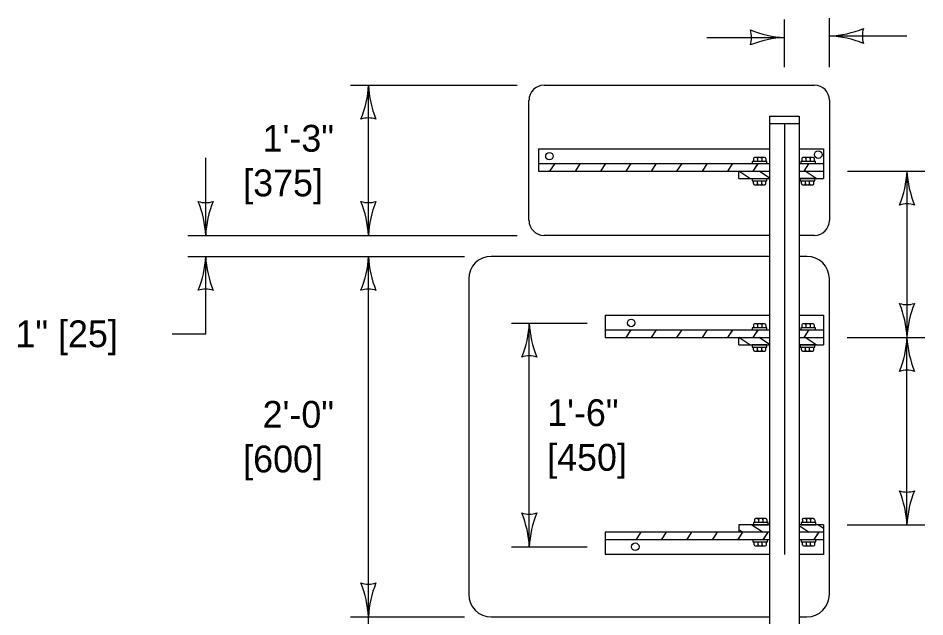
# Model space of a CAD drawing. Extents: x 49991.4 to 50021, y 49987.6 to 50011.4.
# Drawn here: x 50009.026 to 50011.056, y 49996.384 to 49997.726 of the extents above; entities that cross this region are included whole.
import ezdxf

# ---------------------------------------------------------------- set-up
doc = ezdxf.new("R2010")
doc.units = 0
for name, color, linetype in [('Level 1', 7, 'Continuous'), ('Level 2', 7, 'Continuous'), ('Level 3', 7, 'Continuous'), ('Level 4', 7, 'Continuous')]:
    doc.layers.add(name, color=color, linetype=linetype)

msp = doc.modelspace()

# ---------------------------------------------------------------- linework, layer by layer
at = {"layer": 'Level 1'}
for p, q in [((50010.2034, 49997.5753), (50010.809, 49997.5753)), ((50010.1697, 49997.2725), (50010.1697, 49997.5417)), ((50010.8426, 49997.5417), (50010.8426, 49997.2725)), ((50010.7083, 49997.5059), (50010.7083, 49994.5009)), ((50010.7083, 49997.5059), (50010.7748, 49997.5059)), ((50010.7748, 49997.5059), (50010.7748, 49994.5009)), ((50010.7083, 49997.4893), (50010.7748, 49997.4893)), ((50010.1911, 49997.4327), (50010.7073, 49997.4327)), ((50010.1911, 49997.4327), (50010.1911, 49997.3828)), ((50010.7747, 49997.4327), (50010.8291, 49997.4327)), ((50010.8291, 49997.4327), (50010.8291, 49997.366)), ((50010.1911, 49997.3995), (50010.7079, 49997.3995)), ((50010.2167, 49997.3828), (50010.228, 49997.3995)), ((50010.2736, 49997.3828), (50010.2849, 49997.3995)), ((50010.3305, 49997.3828), (50010.3419, 49997.3995)), ((50010.3873, 49997.3828), (50010.3987, 49997.3995)), ((50010.4442, 49997.3828), (50010.4556, 49997.3995)), ((50010.5011, 49997.3828), (50010.5124, 49997.3995)), ((50010.558, 49997.3828), (50010.5693, 49997.3995)), ((50010.6149, 49997.3828), (50010.6262, 49997.3995)), ((50010.6717, 49997.3828), (50010.683, 49997.3995)), ((50010.6717, 49997.3828), (50010.6826, 49997.3989)), ((50010.6717, 49997.3828), (50010.6826, 49997.3989)), ((50010.6717, 49997.3828), (50010.6826, 49997.3989)), ((50010.6717, 49997.3828), (50010.6826, 49997.3989)), ((50010.6717, 49997.3828), (50010.6826, 49997.3989)), ((50010.6722, 49997.4107), (50010.6722, 49997.4045)), ((50010.6973, 49997.4133), (50010.6747, 49997.4133)), ((50010.6974, 49997.4133), (50010.6747, 49997.4133)), ((50010.6815, 49997.4133), (50010.6815, 49997.4045)), ((50010.6908, 49997.4133), (50010.6908, 49997.4045)), ((50010.6999, 49997.4107), (50010.6999, 49997.4045)), ((50010.7747, 49997.3995), (50010.8291, 49997.3995)), ((50010.7747, 49997.3995), (50010.8291, 49997.3995)), ((50010.7747, 49997.3995), (50010.8291, 49997.3995)), ((50010.7805, 49997.4107), (50010.7805, 49997.4045)), ((50010.8056, 49997.4133), (50010.783, 49997.4133)), ((50010.8057, 49997.4133), (50010.783, 49997.4133)), ((50010.7855, 49997.3828), (50010.7964, 49997.3989)), ((50010.7855, 49997.3828), (50010.7964, 49997.3989)), ((50010.7855, 49997.3828), (50010.7964, 49997.3989)), ((50010.7898, 49997.4133), (50010.7898, 49997.4045)), ((50010.7991, 49997.4133), (50010.7991, 49997.4045)), ((50010.8082, 49997.4107), (50010.8082, 49997.4045)), ((50010.1911, 49997.3828), (50010.6397, 49997.3828)), ((50010.6397, 49997.366), (50010.6397, 49997.3828)), ((50010.6397, 49997.3828), (50010.7079, 49997.3828)), ((50010.6642, 49997.366), (50010.6397, 49997.3825)), ((50010.7083, 49997.3668), (50010.6848, 49997.3828)), ((50010.7747, 49997.3828), (50010.8291, 49997.3828)), ((50010.7747, 49997.3828), (50010.8291, 49997.3828)), ((50010.7747, 49997.3828), (50010.8291, 49997.3828)), ((50010.7747, 49997.3828), (50010.8291, 49997.3828)), ((50010.8129, 49997.3659), (50010.7884, 49997.3826)), ((50010.6397, 49997.366), (50010.7083, 49997.366)), ((50010.6724, 49997.3547), (50010.6724, 49997.3609)), ((50010.6815, 49997.3522), (50010.6815, 49997.3609)), ((50010.6909, 49997.3522), (50010.6909, 49997.3609)), ((50010.7001, 49997.3547), (50010.7001, 49997.3609)), ((50010.7749, 49997.366), (50010.8291, 49997.366)), ((50010.7797, 49997.3548), (50010.7797, 49997.361)), ((50010.7888, 49997.3523), (50010.7888, 49997.361)), ((50010.7981, 49997.3523), (50010.7981, 49997.361)), ((50010.8073, 49997.3548), (50010.8073, 49997.361)), ((50010.6749, 49997.3522), (50010.6976, 49997.3522)), ((50010.675, 49997.3522), (50010.6976, 49997.3522)), ((50010.7822, 49997.3523), (50010.8049, 49997.3523)), ((50010.7823, 49997.3523), (50010.8049, 49997.3523)), ((50010.7083, 49997.2388), (50010.2034, 49997.2389)), ((50010.809, 49997.2389), (50010.7748, 49997.2388)), ((50010.7083, 49997.1918), (50010.0853, 49997.1918)), ((50010.7919, 49997.1918), (50010.7748, 49997.1918)), ((50010.0349, 49997.1413), (50010.0349, 49996.4348)), ((50010.8424, 49996.4348), (50010.8424, 49997.1413)), ((50010.3401, 49997.0602), (50010.7073, 49997.0602)), ((50010.3401, 49997.0602), (50010.3401, 49997.0103)), ((50010.7747, 49997.0602), (50010.8291, 49997.0602)), ((50010.8291, 49997.0602), (50010.8291, 49996.9935)), ((50010.6722, 49997.0382), (50010.6722, 49997.032)), ((50010.6973, 49997.0408), (50010.6747, 49997.0408)), ((50010.6974, 49997.0408), (50010.6747, 49997.0408)), ((50010.6815, 49997.0408), (50010.6815, 49997.032)), ((50010.6908, 49997.0408), (50010.6908, 49997.032)), ((50010.6999, 49997.0382), (50010.6999, 49997.032)), ((50010.7805, 49997.0382), (50010.7805, 49997.032)), ((50010.8056, 49997.0408), (50010.783, 49997.0408)), ((50010.8057, 49997.0408), (50010.783, 49997.0408)), ((50010.7898, 49997.0408), (50010.7898, 49997.032)), ((50010.7991, 49997.0408), (50010.7991, 49997.032)), ((50010.8082, 49997.0382), (50010.8082, 49997.032)), ((50010.3401, 49997.027), (50010.7079, 49997.027)), ((50010.3873, 49997.0103), (50010.3987, 49997.027)), ((50010.4442, 49997.0103), (50010.4556, 49997.027)), ((50010.5011, 49997.0103), (50010.5124, 49997.027)), ((50010.558, 49997.0103), (50010.5693, 49997.027)), ((50010.6149, 49997.0103), (50010.6262, 49997.027)), ((50010.6149, 49997.0103), (50010.6258, 49997.0264)), ((50010.6717, 49997.0103), (50010.683, 49997.027)), ((50010.6717, 49997.0103), (50010.6826, 49997.0264)), ((50010.6717, 49997.0103), (50010.6826, 49997.0264)), ((50010.6717, 49997.0103), (50010.6826, 49997.0264)), ((50010.6717, 49997.0103), (50010.6826, 49997.0264)), ((50010.6717, 49997.0103), (50010.6826, 49997.0264)), ((50010.7747, 49997.027), (50010.8279, 49997.027)), ((50010.7747, 49997.027), (50010.8291, 49997.027)), ((50010.7855, 49997.0103), (50010.7968, 49997.027)), ((50010.7855, 49997.0103), (50010.7964, 49997.0264)), ((50010.7855, 49997.0103), (50010.7964, 49997.0264)), ((50010.3401, 49997.0103), (50010.6397, 49997.0103)), ((50010.6397, 49996.9935), (50010.6397, 49997.0103)), ((50010.6397, 49997.0103), (50010.7083, 49997.0103)), ((50010.6642, 49996.9935), (50010.6397, 49997.01)), ((50010.6397, 49996.9935), (50010.7083, 49996.9935)), ((50010.7083, 49996.9943), (50010.6848, 49997.0103)), ((50010.7747, 49997.0103), (50010.8291, 49997.0103)), ((50010.7747, 49997.0103), (50010.8279, 49997.0103)), ((50010.7747, 49997.0103), (50010.8279, 49997.0103)), ((50010.7747, 49997.0103), (50010.8269, 49997.0103)), ((50010.7749, 49996.9935), (50010.8291, 49996.9935)), ((50010.8129, 49996.9935), (50010.7881, 49997.0103)), ((50010.6724, 49996.9822), (50010.6724, 49996.9884)), ((50010.6749, 49996.9797), (50010.6976, 49996.9797)), ((50010.675, 49996.9797), (50010.6976, 49996.9797)), ((50010.6815, 49996.9797), (50010.6815, 49996.9884)), ((50010.6909, 49996.9797), (50010.6909, 49996.9884)), ((50010.7001, 49996.9822), (50010.7001, 49996.9884)), ((50010.7797, 49996.9823), (50010.7797, 49996.9885)), ((50010.7822, 49996.9798), (50010.8049, 49996.9798)), ((50010.7823, 49996.9798), (50010.8049, 49996.9798)), ((50010.7888, 49996.9798), (50010.7888, 49996.9885)), ((50010.7981, 49996.9798), (50010.7981, 49996.9885)), ((50010.8073, 49996.9823), (50010.8073, 49996.9885)), ((50010.6395, 49996.5906), (50010.6395, 49996.5739)), ((50010.7083, 49996.5906), (50010.6395, 49996.5906)), ((50010.669, 49996.5906), (50010.6937, 49996.5738)), ((50010.6745, 49996.6018), (50010.6745, 49996.5956)), ((50010.6996, 49996.6043), (50010.677, 49996.6043)), ((50010.6997, 49996.6043), (50010.677, 49996.6043)), ((50010.6837, 49996.6043), (50010.6837, 49996.5956)), ((50010.693, 49996.6043), (50010.693, 49996.5956)), ((50010.7022, 49996.6018), (50010.7022, 49996.5956)), ((50010.7748, 49996.589), (50010.7971, 49996.5738)), ((50010.8291, 49996.5906), (50010.7749, 49996.5906)), ((50010.7818, 49996.6019), (50010.7818, 49996.5957)), ((50010.8069, 49996.6044), (50010.7842, 49996.6044)), ((50010.8069, 49996.6044), (50010.7842, 49996.6044)), ((50010.791, 49996.6044), (50010.791, 49996.5957)), ((50010.8003, 49996.6044), (50010.8003, 49996.5957)), ((50010.8094, 49996.6019), (50010.8094, 49996.5957)), ((50010.8177, 49996.5906), (50010.8291, 49996.5829)), ((50010.8291, 49996.5906), (50010.8291, 49996.5239)), ((50010.7083, 49996.5738), (50010.3401, 49996.5738)), ((50010.3401, 49996.5738), (50010.3401, 49996.5239)), ((50010.4096, 49996.5571), (50010.421, 49996.5738)), ((50010.4667, 49996.5571), (50010.4779, 49996.5738)), ((50010.5235, 49996.5571), (50010.5347, 49996.5738)), ((50010.5803, 49996.5571), (50010.5916, 49996.5738)), ((50010.6374, 49996.5571), (50010.6486, 49996.5738)), ((50010.6379, 49996.5579), (50010.6472, 49996.5717)), ((50010.6379, 49996.5579), (50010.6472, 49996.5717)), ((50010.6395, 49996.5799), (50010.6486, 49996.5738)), ((50010.7072, 49996.5738), (50010.6395, 49996.5738)), ((50010.6941, 49996.5571), (50010.7053, 49996.5738)), ((50010.6947, 49996.558), (50010.7043, 49996.5723)), ((50010.6947, 49996.558), (50010.7043, 49996.5723)), ((50010.8291, 49996.5738), (50010.7748, 49996.5738)), ((50010.8291, 49996.5738), (50010.7748, 49996.5738)), ((50010.8291, 49996.5738), (50010.7754, 49996.5738)), ((50010.808, 49996.5573), (50010.8191, 49996.5738)), ((50010.808, 49996.5573), (50010.8181, 49996.5723)), ((50010.808, 49996.5573), (50010.8181, 49996.5723)), ((50010.7083, 49996.5571), (50010.3401, 49996.5571)), ((50010.6737, 49996.5459), (50010.6737, 49996.5521)), ((50010.6828, 49996.5433), (50010.6828, 49996.5521)), ((50010.6921, 49996.5433), (50010.6921, 49996.5521)), ((50010.7013, 49996.5459), (50010.7013, 49996.5521)), ((50010.8291, 49996.5571), (50010.7748, 49996.5571)), ((50010.782, 49996.5459), (50010.782, 49996.5521)), ((50010.7911, 49996.5433), (50010.7911, 49996.5521)), ((50010.8004, 49996.5433), (50010.8004, 49996.5521)), ((50010.8096, 49996.5459), (50010.8096, 49996.5521)), ((50010.7072, 49996.5239), (50010.3401, 49996.5239)), ((50010.6761, 49996.5433), (50010.6988, 49996.5433)), ((50010.6762, 49996.5433), (50010.6988, 49996.5433)), ((50010.8291, 49996.5239), (50010.7749, 49996.5239)), ((50010.7844, 49996.5433), (50010.8071, 49996.5433)), ((50010.7845, 49996.5433), (50010.8071, 49996.5433)), ((50010.0853, 49996.3843), (50010.7083, 49996.3843)), ((50010.7748, 49996.3843), (50010.7919, 49996.3843))]:
    msp.add_line(p, q, dxfattribs=at)
for points in [[(50010.7026, 49997.3997), (50010.7026, 49997.4043), (50010.6698, 49997.4043), (50010.6698, 49997.3997)], [(50010.8109, 49997.3997), (50010.8109, 49997.4043), (50010.7781, 49997.4043), (50010.7781, 49997.3997)], [(50010.6697, 49997.3658), (50010.6697, 49997.3611), (50010.7025, 49997.3611), (50010.7025, 49997.3658)], [(50010.7769, 49997.3659), (50010.7769, 49997.3612), (50010.8098, 49997.3612), (50010.8098, 49997.3659)], [(50010.7026, 49997.0272), (50010.7026, 49997.0318), (50010.6698, 49997.0318), (50010.6698, 49997.0272)], [(50010.8109, 49997.0272), (50010.8109, 49997.0318), (50010.7781, 49997.0318), (50010.7781, 49997.0272)], [(50010.6697, 49996.9933), (50010.6697, 49996.9886), (50010.7025, 49996.9886), (50010.7025, 49996.9933)], [(50010.7769, 49996.9934), (50010.7769, 49996.9887), (50010.8098, 49996.9887), (50010.8098, 49996.9934)], [(50010.7049, 49996.5907), (50010.7049, 49996.5954), (50010.6721, 49996.5954), (50010.6721, 49996.5907)], [(50010.8122, 49996.5908), (50010.8122, 49996.5955), (50010.7793, 49996.5955), (50010.7793, 49996.5908)], [(50010.6709, 49996.5569), (50010.6709, 49996.5523), (50010.7038, 49996.5523), (50010.7038, 49996.5569)], [(50010.7792, 49996.5569), (50010.7792, 49996.5523), (50010.8121, 49996.5523), (50010.8121, 49996.5569)]]:
    msp.add_lwpolyline(points, close=True, dxfattribs=at)
for centre in [(50010.2156, 49997.4163), (50010.8174, 49997.4198), (50010.3985, 49997.0426), (50010.4078, 49996.5414)]:
    msp.add_circle(centre, 0.00843, dxfattribs=at)
for centre, radius, start, end in [((50010.2034, 49997.5417), 0.0336, 90, 180), ((50010.809, 49997.5417), 0.0336, 0, 90), ((50010.6748, 49997.4107), 0.00257, 90, 180), ((50010.6789, 49997.4107), 0.00257, 0, 90), ((50010.684, 49997.4107), 0.00257, 90, 180), ((50010.6881, 49997.4107), 0.00257, 0, 90), ((50010.6932, 49997.4107), 0.00257, 90, 180), ((50010.6973, 49997.4107), 0.00257, 0, 90), ((50010.7831, 49997.4107), 0.00257, 90, 180), ((50010.7872, 49997.4107), 0.00257, 0, 90), ((50010.7923, 49997.4107), 0.00257, 90, 180), ((50010.7964, 49997.4107), 0.00257, 0, 90), ((50010.8015, 49997.4107), 0.00257, 90, 180), ((50010.8056, 49997.4107), 0.00257, 0, 90), ((50010.675, 49997.3547), 0.00257, 180, 270), ((50010.6791, 49997.3547), 0.00257, 270, 0), ((50010.6842, 49997.3547), 0.00257, 180, 270), ((50010.6883, 49997.3547), 0.00257, 270, 0), ((50010.6934, 49997.3547), 0.00257, 180, 270), ((50010.6975, 49997.3547), 0.00257, 270, 0), ((50010.7823, 49997.3548), 0.00257, 180, 270), ((50010.7863, 49997.3548), 0.00257, 270, 0), ((50010.7915, 49997.3548), 0.00257, 180, 270), ((50010.7955, 49997.3548), 0.00257, 270, 0), ((50010.8007, 49997.3548), 0.00257, 180, 270), ((50010.8048, 49997.3548), 0.00257, 270, 0), ((50010.2034, 49997.2725), 0.0336, 180, 270), ((50010.809, 49997.2725), 0.0336, 270, 0), ((50010.0853, 49997.1413), 0.0505, 90, 180), ((50010.7919, 49997.1413), 0.0505, 0, 90), ((50010.6748, 49997.0382), 0.00257, 90, 180), ((50010.6789, 49997.0382), 0.00257, 0, 90), ((50010.684, 49997.0382), 0.00257, 90, 180), ((50010.6881, 49997.0382), 0.00257, 0, 90), ((50010.6932, 49997.0382), 0.00257, 90, 180), ((50010.6973, 49997.0382), 0.00257, 0, 90), ((50010.7831, 49997.0382), 0.00257, 90, 180), ((50010.7872, 49997.0382), 0.00257, 0, 90), ((50010.7923, 49997.0382), 0.00257, 90, 180), ((50010.7964, 49997.0382), 0.00257, 0, 90), ((50010.8015, 49997.0382), 0.00257, 90, 180), ((50010.8056, 49997.0382), 0.00257, 0, 90), ((50010.675, 49996.9822), 0.00257, 180, 270), ((50010.6791, 49996.9822), 0.00257, 270, 0), ((50010.6842, 49996.9822), 0.00257, 180, 270), ((50010.6883, 49996.9822), 0.00257, 270, 0), ((50010.6934, 49996.9822), 0.00257, 180, 270), ((50010.6975, 49996.9822), 0.00257, 270, 0), ((50010.7823, 49996.9823), 0.00257, 180, 270), ((50010.7863, 49996.9823), 0.00257, 270, 0), ((50010.7915, 49996.9823), 0.00257, 180, 270), ((50010.7955, 49996.9823), 0.00257, 270, 0), ((50010.8007, 49996.9823), 0.00257, 180, 270), ((50010.8048, 49996.9823), 0.00257, 270, 0), ((50010.6771, 49996.6018), 0.00257, 90, 180), ((50010.6812, 49996.6018), 0.00257, 0, 90), ((50010.6863, 49996.6018), 0.00257, 90, 180), ((50010.6904, 49996.6018), 0.00257, 0, 90), ((50010.6955, 49996.6018), 0.00257, 90, 180), ((50010.6996, 49996.6018), 0.00257, 0, 90), ((50010.7843, 49996.6019), 0.00257, 90, 180), ((50010.7884, 49996.6019), 0.00257, 0, 90), ((50010.7936, 49996.6019), 0.00257, 90, 180), ((50010.7976, 49996.6019), 0.00257, 0, 90), ((50010.8028, 49996.6019), 0.00257, 90, 180), ((50010.8068, 49996.6019), 0.00257, 0, 90), ((50010.6763, 49996.5459), 0.00257, 180, 270), ((50010.6803, 49996.5459), 0.00257, 270, 0), ((50010.6855, 49996.5459), 0.00257, 180, 270), ((50010.6895, 49996.5459), 0.00257, 270, 0), ((50010.6947, 49996.5459), 0.00257, 180, 270), ((50010.6987, 49996.5459), 0.00257, 270, 0), ((50010.7846, 49996.5459), 0.00257, 180, 270), ((50010.7886, 49996.5459), 0.00257, 270, 0), ((50010.7938, 49996.5459), 0.00257, 180, 270), ((50010.7978, 49996.5459), 0.00257, 270, 0), ((50010.803, 49996.5459), 0.00257, 180, 270), ((50010.807, 49996.5459), 0.00257, 270, 0), ((50010.0853, 49996.4348), 0.0505, 180, 270), ((50010.7919, 49996.4348), 0.0505, 270, 0)]:
    msp.add_arc(centre, radius, start, end, dxfattribs=at)
at = {"layer": 'Level 3'}
for p, q in [((50010.7416, 49997.6153), (50010.7416, 49997.7222)), ((50010.8426, 49997.6153), (50010.8426, 49997.7255)), ((50010.5682, 49997.6822), (50010.7416, 49997.6822)), ((50010.8426, 49997.6855), (50011.016, 49997.6855)), ((50009.7703, 49997.5753), (50010.1434, 49997.5753)), ((50009.8103, 49997.2388), (50009.8103, 49997.5753)), ((50009.4459, 49997.2388), (50009.4459, 49997.4122)), ((50010.8827, 49997.3828), (50011.0561, 49997.3828)), ((50011.0161, 49997.3828), (50011.0161, 49997.0103)), ((50009.4059, 49997.2388), (50010.1434, 49997.2388)), ((50009.4059, 49997.1918), (50010.0253, 49997.1918)), ((50009.4459, 49997.0184), (50009.4459, 49997.1918)), ((50009.8103, 49996.3843), (50009.8103, 49997.1918)), ((50010.1305, 49997.0424), (50010.3001, 49997.0424)), ((50010.1705, 49996.541), (50010.1705, 49997.0424)), ((50009.371, 49997.0184), (50009.4459, 49997.0184)), ((50010.8824, 49997.0103), (50011.0561, 49997.0103)), ((50011.0161, 49996.5906), (50011.0161, 49997.0103)), ((50010.8824, 49996.5906), (50011.0561, 49996.5906)), ((50010.1305, 49996.541), (50010.3001, 49996.541)), ((50009.7703, 49996.3843), (50010.0253, 49996.3843)), ((50009.8103, 49994.5009), (50009.8103, 49996.3843))]:
    msp.add_line(p, q, dxfattribs=at)
for centre, radius, start, end in [((50010.8312, 49997.9182), 0.233, 272.8273, 292.0772), ((50010.9709, 49997.6855), 0.0548, 162.1388, 197.8612), ((50010.7508, 49997.9043), 0.2223, 247.456, 267.6395), ((50010.6134, 49997.6822), 0.0548, 342.1388, 17.8612), ((50010.7531, 49997.4495), 0.233, 92.8273, 112.0772), ((50010.8335, 49997.4634), 0.2223, 67.456, 87.6395), ((50009.5882, 49997.5845), 0.2223, 337.456, 357.6395), ((50010.043, 49997.5868), 0.233, 182.8273, 202.0772), ((50009.8103, 49997.4471), 0.0548, 72.1388, 107.8612), ((50010.794, 49997.392), 0.2223, 337.456, 357.6395), ((50011.2488, 49997.3943), 0.233, 182.8273, 202.0772), ((50009.4459, 49997.367), 0.0548, 252.1388, 287.8612), ((50009.2132, 49997.2273), 0.233, 2.8273, 22.0772), ((50009.668, 49997.2296), 0.2223, 157.456, 177.6395), ((50009.8103, 49997.367), 0.0548, 252.1388, 287.8612), ((50009.5776, 49997.2273), 0.233, 2.8273, 22.0772), ((50010.0324, 49997.2296), 0.2223, 157.456, 177.6395), ((50011.0161, 49997.2546), 0.0548, 72.1388, 107.8612), ((50009.2238, 49997.201), 0.2223, 337.456, 357.6395), ((50009.6786, 49997.2033), 0.233, 182.8273, 202.0772), ((50009.5882, 49997.201), 0.2223, 337.456, 357.6395), ((50010.043, 49997.2033), 0.233, 182.8273, 202.0772), ((50009.4459, 49997.0636), 0.0548, 72.1388, 107.8612), ((50009.8103, 49997.0636), 0.0548, 72.1388, 107.8612), ((50011.0161, 49997.1385), 0.0548, 252.1388, 287.8612), ((50010.7834, 49996.9988), 0.233, 2.8273, 22.0772), ((50011.2382, 49997.0011), 0.2223, 157.456, 177.6395), ((50009.9484, 49997.0516), 0.2223, 337.456, 357.6395), ((50010.4032, 49997.0539), 0.233, 182.8273, 202.0772), ((50010.794, 49997.0195), 0.2223, 337.456, 357.6395), ((50011.2488, 49997.0218), 0.233, 182.8273, 202.0772), ((50010.1705, 49996.9142), 0.0548, 72.1388, 107.8612), ((50011.0161, 49996.8821), 0.0548, 72.1388, 107.8612), ((50011.0161, 49996.7188), 0.0548, 252.1388, 287.8612), ((50010.7834, 49996.5791), 0.233, 2.8273, 22.0772), ((50011.2382, 49996.5814), 0.2223, 157.456, 177.6395), ((50010.1705, 49996.6692), 0.0548, 252.1388, 287.8612), ((50009.9378, 49996.5295), 0.233, 2.8273, 22.0772), ((50010.3926, 49996.5318), 0.2223, 157.456, 177.6395), ((50009.8103, 49996.5125), 0.0548, 252.1388, 287.8612), ((50009.5776, 49996.3728), 0.233, 2.8273, 22.0772), ((50010.0324, 49996.3751), 0.2223, 157.456, 177.6395)]:
    msp.add_arc(centre, radius, start, end, dxfattribs=at)
at = {"layer": 'Level 4'}
msp.add_line((50010.7416, 49997.4893), (50010.7416, 49996.5239), dxfattribs=at)

# ---------------------------------------------------------------- texts
at = {"layer": 'Level 2'}
for s, p in [('1\'-3"', (50009.5734, 49997.4264)), ('[375]', (50009.5299, 49997.3264)), ('1" [25]', (50009.0199, 49996.9884)), ('2\'-0"', (50009.5734, 49996.808)), ('1\'-6"', (50010.2105, 49996.8117)), ('[600]', (50009.5299, 49996.708)), ('[450]', (50010.2105, 49996.7117))]:
    msp.add_text(s, height=0.06, dxfattribs=at).set_placement(p)

doc.saveas('drawing.dxf')
